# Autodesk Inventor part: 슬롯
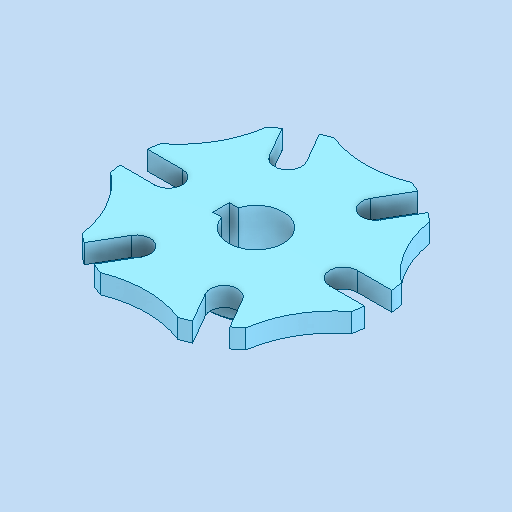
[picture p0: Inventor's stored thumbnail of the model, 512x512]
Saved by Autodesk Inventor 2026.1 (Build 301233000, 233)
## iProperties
Created: 2025-09
Part Number: 슬롯
Material: 강철, 합금
Document SubType Name: Modeling
Designer: PC-30
Density: 7.73 g/cm^3
Appearance: 기본값
Author: jhkim
Sending System: Autodesk Inventor 2026
Preprocessor: ST-DEVELOPER v20.1
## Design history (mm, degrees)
feature "솔리드1"
node "솔리드2"
